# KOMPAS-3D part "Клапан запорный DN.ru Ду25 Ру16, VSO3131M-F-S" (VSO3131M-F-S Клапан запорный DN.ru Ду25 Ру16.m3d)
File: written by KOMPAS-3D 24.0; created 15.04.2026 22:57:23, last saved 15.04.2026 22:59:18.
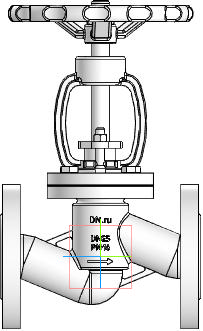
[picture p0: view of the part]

Document properties: Автор: R2D2; Полное имя файла: E:\Работа\Зайцев\VSO3131M-F-S Клапан запорный DN.ru Ду15-100 Ру16\DN25\VSO3131M-F-S Клапан запорный DN.ru Ду25 Ру16.m3d

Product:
- Part/product: Клапан запорный DN.ru Ду25 Ру16  | designation VSO3131M-F-S
    Масса: 5.1
    Раздел спецификации: Прочие изделия
    Примечание: D090-02948

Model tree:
1. Операция без истории:2

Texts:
  Точка начала. Х
  Точка начала. Y
  Точка начала. Z
  VSO3131M-F-S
